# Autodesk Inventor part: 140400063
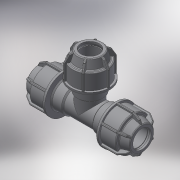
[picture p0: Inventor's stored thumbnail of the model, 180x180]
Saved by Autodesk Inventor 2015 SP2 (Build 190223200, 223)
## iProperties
Created: 2017-08
Part Number: 140400063
Material: Generic
Description: PLASSON L.14 TEE (SILVER) 63-63-63
Document SubType Name: Modeling
Designer: KIM
Density: 1 g/cm^3
Appearance: Default
Author: KIM
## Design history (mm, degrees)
derived "140400.ipt"
feature "Solid1::140400.ipt"
tag "TaggingFeature1"
body "Solid1"
other parameters: "d1" = 63, "d2" = 82, "d4" = 15 deg, "d5" = 54.12, "d6" = 17.8596, "d10" = 106, "d16" = 64.26, "d17" = 4.1, "d22" = 88.2, "d24" = 4.1, "d25" = 95.4, "d26" = 79.5, "d27" = 4.1, "d28" = 135 deg, "d29" = 2.46, "d31" = 3.15, "d46" = 150 deg, "d49" = 5.3, "d50" = 0, "d58" = 1.89, "d61" = 360 deg, "d63" = 56.7, "d64" = 119.5, "d78" = 180 deg, "d80" = 79.38, "d81" = 4.41, "d84" = 8.2, "d86" = 0, "d88" = 0, "d90" = 0, "d92" = 180 deg, "d_" = 63, "G_" = 18.631, "E_" = 106, "H_" = 239, "l_" = 82, "l_2" = 19
